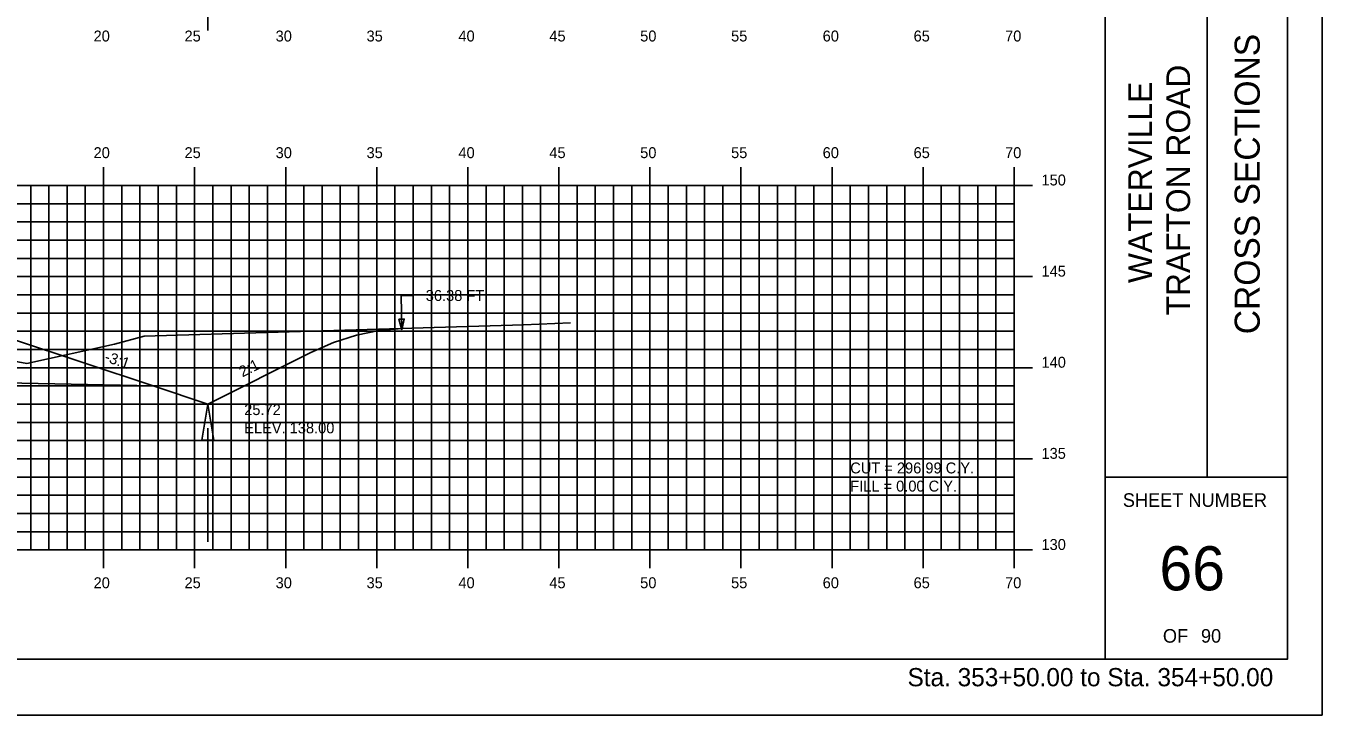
# Model space of a CAD drawing. Extents: x 1145194 to 1145364, y 608981 to 609091.
# Drawn here: x 1145292.9 to 1145364, y 608981.3 to 609019.1 of the extents above; entities that cross this region are included whole.
import ezdxf

# ---------------------------------------------------------------- set-up
doc = ezdxf.new("R2010")
doc.units = 0
for name, color, linetype in [('ANNOTATION', 7, 'Continuous'), ('BORDER', 7, 'Continuous'), ('D_Drainage_Ditch_Line', 7, 'Continuous'), ('D_Roadway_SlopeLines', 7, 'Continuous'), ('D_Roadway_SubGrade', 7, 'Continuous'), ('D_Text_Standard', 7, 'Continuous'), ('H_V ANNOTATION', 7, 'Continuous'), ('HIGHWAY_TITLE', 7, 'Continuous'), ('MAJOR', 7, 'Continuous'), ('MINOR', 7, 'Continuous'), ('PLOT BOUNDARY', 7, 'Continuous'), ('S_Roadway_Centerline', 7, 'Continuous')]:
    doc.layers.add(name, color=color, linetype=linetype)

msp = doc.modelspace()

# ---------------------------------------------------------------- linework, layer by layer
msp.add_lwpolyline([(1145239.447, 609003.059), (1145240.697, 609002.984), (1145241.947, 609002.751), (1145243.197, 609002.362), (1145244.447, 609001.816), (1145251.407, 608998.336), (1145254.407, 608999.336), (1145262.131, 609001.91), (1145262.132, 609001.91), (1145266.132, 609002.07), (1145277.132, 609002.29), (1145288.132, 609002.07), (1145292.132, 609001.91), (1145299.855, 608999.336), (1145302.855, 608998.336), (1145308.513, 609001.164), (1145309.763, 609001.716), (1145311.013, 609002.121), (1145312.263, 609002.379), (1145313.513, 609002.49)])
at = {"layer": 'BORDER'}
for p, q in [((1145352.132, 608984.335), (1145352.132, 609089.335)), ((1145357.723, 608994.338), (1145357.723, 609029.338)), ((1145352.132, 608994.338), (1145362.132, 608994.338))]:
    msp.add_line(p, q, dxfattribs=at)
msp.add_lwpolyline([(1145202.132, 608984.335), (1145362.132, 608984.335), (1145362.132, 609089.335), (1145202.132, 609089.335)], close=True, dxfattribs=at)
at = {"layer": 'D_Drainage_Ditch_Line'}
for p, q in [((1145302.856, 609025.082), (1145302.855, 609018.839)), ((1145302.856, 608997.023), (1145302.855, 608990.78))]:
    msp.add_line(p, q, dxfattribs=at)
msp.add_lwpolyline([(1145303.184, 608996.367), (1145302.527, 608996.367), (1145302.855, 608998.336)], close=True, dxfattribs=at)
at = {"layer": 'D_Roadway_SlopeLines'}
for points in [[(1145302.855, 608998.336), (1145308.513, 609001.164), (1145309.763, 609001.716), (1145311.013, 609002.121), (1145312.263, 609002.379), (1145313.513, 609002.49)], [(1145299.855, 608999.336), (1145302.855, 608998.336)]]:
    msp.add_lwpolyline(points, dxfattribs=at)
at = {"layer": 'D_Roadway_SubGrade'}
msp.add_lwpolyline([(1145288.132, 609001.653), (1145288.132, 609001.82), (1145292.132, 609001.66), (1145292.132, 609001.91), (1145292.132, 609001.91), (1145299.855, 608999.336), (1145288.132, 608999.57)], close=True, dxfattribs=at)
at = {"layer": 'D_Text_Standard'}
msp.add_lwpolyline([(1145313.513, 609002.414), (1145313.465, 609004.299), (1145314.145, 609004.299)], dxfattribs=at)
msp.add_lwpolyline([(1145313.513, 609002.414), (1145313.353, 609002.992), (1145313.643, 609003)], close=True, dxfattribs=at)
at = {"layer": 'MAJOR'}
for p, q in [((1145297.132, 609011.337), (1145297.132, 609010.335)), ((1145302.132, 609011.337), (1145302.132, 609010.335)), ((1145307.132, 609011.337), (1145307.132, 609010.335)), ((1145312.132, 609011.337), (1145312.132, 609010.335)), ((1145317.132, 609011.337), (1145317.132, 609010.335)), ((1145322.132, 609011.337), (1145322.132, 609010.335)), ((1145327.132, 609011.337), (1145327.132, 609010.335)), ((1145332.132, 609011.337), (1145332.132, 609010.335)), ((1145337.132, 609011.337), (1145337.132, 609010.335)), ((1145342.132, 609011.337), (1145342.132, 609010.335)), ((1145347.132, 609011.337), (1145347.132, 609010.335)), ((1145207.132, 609010.335), (1145347.132, 609010.335)), ((1145207.132, 609010.335), (1145347.132, 609010.335)), ((1145297.132, 608990.335), (1145297.132, 609010.335)), ((1145302.132, 608990.335), (1145302.132, 609010.335)), ((1145307.132, 608990.335), (1145307.132, 609010.335)), ((1145312.132, 608990.335), (1145312.132, 609010.335)), ((1145317.132, 608990.335), (1145317.132, 609010.335)), ((1145322.132, 608990.335), (1145322.132, 609010.335)), ((1145327.132, 608990.335), (1145327.132, 609010.335)), ((1145332.132, 608990.335), (1145332.132, 609010.335)), ((1145337.132, 608990.335), (1145337.132, 609010.335)), ((1145342.132, 608990.335), (1145342.132, 609010.335)), ((1145348.134, 609010.335), (1145346.13, 609010.335)), ((1145347.132, 608990.335), (1145347.132, 609010.335)), ((1145347.132, 608990.335), (1145347.132, 609010.335)), ((1145207.132, 609005.335), (1145347.132, 609005.335)), ((1145348.134, 609005.335), (1145346.13, 609005.335)), ((1145207.132, 609000.335), (1145347.132, 609000.335)), ((1145348.134, 609000.335), (1145346.13, 609000.335)), ((1145207.132, 608995.335), (1145347.132, 608995.335)), ((1145348.134, 608995.335), (1145346.13, 608995.335)), ((1145207.132, 608990.335), (1145347.132, 608990.335)), ((1145207.132, 608990.335), (1145347.132, 608990.335)), ((1145297.132, 608989.333), (1145297.132, 608990.335)), ((1145302.132, 608989.333), (1145302.132, 608990.335)), ((1145307.132, 608989.333), (1145307.132, 608990.335)), ((1145312.132, 608989.333), (1145312.132, 608990.335)), ((1145317.132, 608989.333), (1145317.132, 608990.335)), ((1145322.132, 608989.333), (1145322.132, 608990.335)), ((1145327.132, 608989.333), (1145327.132, 608990.335)), ((1145332.132, 608989.333), (1145332.132, 608990.335)), ((1145337.132, 608989.333), (1145337.132, 608990.335)), ((1145342.132, 608989.333), (1145342.132, 608990.335)), ((1145348.134, 608990.335), (1145346.13, 608990.335)), ((1145347.132, 608989.333), (1145347.132, 608990.335))]:
    msp.add_line(p, q, dxfattribs=at)
at = {"layer": 'MINOR'}
for p, q in [((1145293.132, 608990.335), (1145293.132, 609010.335)), ((1145294.132, 608990.335), (1145294.132, 609010.335)), ((1145295.132, 608990.335), (1145295.132, 609010.335)), ((1145296.132, 608990.335), (1145296.132, 609010.335)), ((1145298.132, 608990.335), (1145298.132, 609010.335)), ((1145299.132, 608990.335), (1145299.132, 609010.335)), ((1145300.132, 608990.335), (1145300.132, 609010.335)), ((1145301.132, 608990.335), (1145301.132, 609010.335)), ((1145303.132, 608990.335), (1145303.132, 609010.335)), ((1145304.132, 608990.335), (1145304.132, 609010.335)), ((1145305.132, 608990.335), (1145305.132, 609010.335)), ((1145306.132, 608990.335), (1145306.132, 609010.335)), ((1145308.132, 608990.335), (1145308.132, 609010.335)), ((1145309.132, 608990.335), (1145309.132, 609010.335)), ((1145310.132, 608990.335), (1145310.132, 609010.335)), ((1145311.132, 608990.335), (1145311.132, 609010.335)), ((1145313.132, 608990.335), (1145313.132, 609010.335)), ((1145314.132, 608990.335), (1145314.132, 609010.335)), ((1145315.132, 608990.335), (1145315.132, 609010.335)), ((1145316.132, 608990.335), (1145316.132, 609010.335)), ((1145318.132, 608990.335), (1145318.132, 609010.335)), ((1145319.132, 608990.335), (1145319.132, 609010.335)), ((1145320.132, 608990.335), (1145320.132, 609010.335)), ((1145321.132, 608990.335), (1145321.132, 609010.335)), ((1145323.132, 608990.335), (1145323.132, 609010.335)), ((1145324.132, 608990.335), (1145324.132, 609010.335)), ((1145325.132, 608990.335), (1145325.132, 609010.335)), ((1145326.132, 608990.335), (1145326.132, 609010.335)), ((1145328.132, 608990.335), (1145328.132, 609010.335)), ((1145329.132, 608990.335), (1145329.132, 609010.335)), ((1145330.132, 608990.335), (1145330.132, 609010.335)), ((1145331.132, 608990.335), (1145331.132, 609010.335)), ((1145333.132, 608990.335), (1145333.132, 609010.335)), ((1145334.132, 608990.335), (1145334.132, 609010.335)), ((1145335.132, 608990.335), (1145335.132, 609010.335)), ((1145336.132, 608990.335), (1145336.132, 609010.335)), ((1145338.132, 608990.335), (1145338.132, 609010.335)), ((1145339.132, 608990.335), (1145339.132, 609010.335)), ((1145340.132, 608990.335), (1145340.132, 609010.335)), ((1145341.132, 608990.335), (1145341.132, 609010.335)), ((1145343.132, 608990.335), (1145343.132, 609010.335)), ((1145344.132, 608990.335), (1145344.132, 609010.335)), ((1145345.132, 608990.335), (1145345.132, 609010.335)), ((1145346.132, 608990.335), (1145346.132, 609010.335)), ((1145207.132, 609009.335), (1145347.132, 609009.335)), ((1145347.132, 609009.335), (1145346.13, 609009.335)), ((1145207.132, 609008.335), (1145347.132, 609008.335)), ((1145347.132, 609008.335), (1145346.13, 609008.335)), ((1145207.132, 609007.335), (1145347.132, 609007.335)), ((1145347.132, 609007.335), (1145346.13, 609007.335)), ((1145207.132, 609006.335), (1145347.132, 609006.335)), ((1145347.132, 609006.335), (1145346.13, 609006.335)), ((1145207.132, 609004.335), (1145347.132, 609004.335)), ((1145347.132, 609004.335), (1145346.13, 609004.335)), ((1145207.132, 609003.335), (1145347.132, 609003.335)), ((1145347.132, 609003.335), (1145346.13, 609003.335)), ((1145207.132, 609002.335), (1145347.132, 609002.335)), ((1145347.132, 609002.335), (1145346.13, 609002.335)), ((1145207.132, 609001.335), (1145347.132, 609001.335)), ((1145347.132, 609001.335), (1145346.13, 609001.335)), ((1145207.132, 608999.335), (1145347.132, 608999.335)), ((1145347.132, 608999.335), (1145346.13, 608999.335)), ((1145207.132, 608998.335), (1145347.132, 608998.335)), ((1145347.132, 608998.335), (1145346.13, 608998.335)), ((1145207.132, 608997.335), (1145347.132, 608997.335)), ((1145347.132, 608997.335), (1145346.13, 608997.335)), ((1145207.132, 608996.335), (1145347.132, 608996.335)), ((1145347.132, 608996.335), (1145346.13, 608996.335)), ((1145207.132, 608994.335), (1145347.132, 608994.335)), ((1145347.132, 608994.335), (1145346.13, 608994.335)), ((1145207.132, 608993.335), (1145347.132, 608993.335)), ((1145347.132, 608993.335), (1145346.13, 608993.335)), ((1145207.132, 608992.335), (1145347.132, 608992.335)), ((1145347.132, 608992.335), (1145346.13, 608992.335)), ((1145207.132, 608991.335), (1145347.132, 608991.335)), ((1145347.132, 608991.335), (1145346.13, 608991.335))]:
    msp.add_line(p, q, dxfattribs=at)
at = {"layer": 'PLOT BOUNDARY'}
msp.add_lwpolyline([(1145194.039, 608981.276), (1145364.039, 608981.276), (1145364.039, 609091.276), (1145194.039, 609091.276)], close=True, dxfattribs=at)
at = {"layer": 'S_Roadway_Centerline'}
msp.add_lwpolyline([(1145223.166, 609003.006), (1145241.903, 609003.066), (1145248.778, 609002.948), (1145254.838, 609001.419), (1145256.893, 609000.916), (1145259.182, 609001.542), (1145260.082, 609001.809), (1145262.139, 609001.946), (1145262.599, 609001.976), (1145271.221, 609002.19), (1145273.977, 609002.245), (1145276.689, 609002.152), (1145284.89, 609001.824), (1145287.007, 609001.621), (1145287.938, 609001.527), (1145288.943, 609001.294), (1145292.925, 609000.571), (1145297.727, 609001.626), (1145299.356, 609002.061), (1145320.182, 609002.692), (1145322.779, 609002.793)], dxfattribs=at)

# ---------------------------------------------------------------- texts
at = {"layer": 'ANNOTATION'}
for s, rotation, p in [('-3:1', 341.56521, (1145297.143, 609000.694)), ('2:1', 26.56505, (1145304.757, 608999.804))]:
    msp.add_text(s, height=0.6, rotation=rotation, dxfattribs=at).set_placement(p)
at = {"layer": 'BORDER'}
msp.add_text('CROSS SECTIONS', height=1.37787, rotation=90, dxfattribs=at).set_placement((1145360.617, 609002.172))
for s, height, p in [('SHEET NUMBER', 0.74527, (1145353.098, 608992.701)), ('66', 2.4194, (1145355.108, 608988.118)), ('OF', 0.7453, (1145355.299, 608985.248)), ('90', 0.7453, (1145357.389, 608985.248))]:
    msp.add_text(s, height=height, dxfattribs=at).set_placement(p)
at = {"layer": 'D_Text_Standard'}
for s, p in [('36.38 FT', (1145314.825, 609003.999)), ('25.72', (1145304.856, 608997.736)), ('ELEV. 138.00', (1145304.856, 608996.734)), ('CUT = 296.99 C.Y.', (1145338.132, 608994.535)), ('FILL = 0.00 C.Y.', (1145338.132, 608993.539))]:
    msp.add_text(s, height=0.6, dxfattribs=at).set_placement(p)
at = {"layer": 'H_V ANNOTATION'}
for s, height, p in [('20', 0.6, (1145296.586, 609018.235)), ('25', 0.6, (1145301.578, 609018.235)), ('30', 0.6, (1145306.581, 609018.235)), ('35', 0.6, (1145311.573, 609018.235)), ('40', 0.6, (1145316.618, 609018.235)), ('45', 0.6, (1145321.61, 609018.235)), ('50', 0.6, (1145326.597, 609018.235)), ('55', 0.6, (1145331.589, 609018.235)), ('60', 0.6, (1145336.618, 609018.235)), ('65', 0.6, (1145341.61, 609018.235)), ('70', 0.6, (1145346.634, 609018.235)), ('20', 0.6, (1145296.586, 609011.835)), ('25', 0.6, (1145301.578, 609011.835)), ('30', 0.6, (1145306.581, 609011.835)), ('35', 0.6, (1145311.573, 609011.835)), ('40', 0.6, (1145316.618, 609011.835)), ('45', 0.6, (1145321.61, 609011.835)), ('50', 0.6, (1145326.597, 609011.835)), ('55', 0.6, (1145331.589, 609011.835)), ('60', 0.6, (1145336.618, 609011.835)), ('65', 0.6, (1145341.61, 609011.835)), ('70', 0.6, (1145346.634, 609011.835)), ('150', 0.6, (1145348.632, 609010.335)), ('145', 0.6, (1145348.632, 609005.335)), ('140', 0.6, (1145348.632, 609000.335)), ('135', 0.6, (1145348.632, 608995.335)), ('130', 0.6, (1145348.632, 608990.335)), ('20', 0.6, (1145296.586, 608988.235)), ('25', 0.6, (1145301.578, 608988.235)), ('30', 0.6, (1145306.581, 608988.235)), ('35', 0.6, (1145311.573, 608988.235)), ('40', 0.6, (1145316.618, 608988.235)), ('45', 0.6, (1145321.61, 608988.235)), ('50', 0.6, (1145326.597, 608988.235)), ('55', 0.6, (1145331.589, 608988.235)), ('60', 0.6, (1145336.618, 608988.235)), ('65', 0.6, (1145341.61, 608988.235)), ('70', 0.6, (1145346.634, 608988.235)), ('Sta. 353+50.00 to Sta. 354+50.00', 1.0002, (1145341.278, 608982.855))]:
    msp.add_text(s, height=height, dxfattribs=at).set_placement(p)
at = {"layer": 'HIGHWAY_TITLE'}
for s, height, p in [('TRAFTON ROAD', 1.30428, (1145356.792, 609003.201)), ('WATERVILLE', 1.3043, (1145354.705, 609004.98))]:
    msp.add_text(s, height=height, rotation=90, dxfattribs=at).set_placement(p)

doc.saveas('drawing.dxf')
